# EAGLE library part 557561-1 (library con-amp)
AMP connector
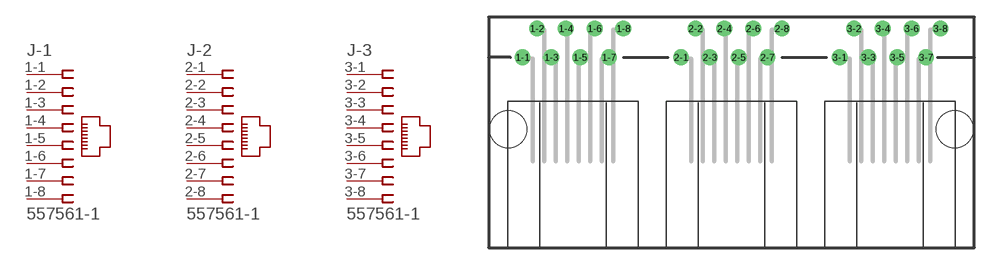
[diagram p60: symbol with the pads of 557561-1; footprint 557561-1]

Designator prefix J; gates -1=JACK8 -2=JACK8 -3=JACK8

## 557561-1 (MPN: 5557561-1; OC_FARNELL: 1769882; OC_NEWARK: 19R2785)  [557561-1]
1-1  -1:1  pas
1-2  -1:2  pas
1-3  -1:3  pas
1-4  -1:4  pas
1-5  -1:5  pas
1-6  -1:6  pas
1-7  -1:7  pas
1-8  -1:8  pas
2-1  -2:1  pas
2-2  -2:2  pas
2-3  -2:3  pas
2-4  -2:4  pas
2-5  -2:5  pas
2-6  -2:6  pas
2-7  -2:7  pas
2-8  -2:8  pas
3-1  -3:1  pas
3-2  -3:2  pas
3-3  -3:3  pas
3-4  -3:4  pas
3-5  -3:5  pas
3-6  -3:6  pas
3-7  -3:7  pas
3-8  -3:8  pas

## Footprint 557561-1 (pad centres in mm)
Modular Jack
drill 0.889 round: 1-1 -18.415,6.35; 1-2 -17.145,8.89; 1-3 -15.875,6.35; 1-4 -14.605,8.89; 1-5 -13.335,6.35; 1-6 -12.065,8.89; 1-7 -10.795,6.35; 1-8 -9.525,8.89; 2-1 -4.445,6.35; 2-2 -3.175,8.89; 2-3 -1.905,6.35; 2-4 -0.635,8.89; 2-5 0.635,6.35; 2-6 1.905,8.89; 2-7 3.175,6.35; 2-8 4.445,8.89; 3-1 9.525,6.35; 3-2 10.795,8.89; 3-3 12.065,6.35; 3-4 13.335,8.89; 3-5 14.605,6.35; 3-6 15.875,8.89; 3-7 17.145,6.35; 3-8 18.415,8.89
hole 3.251 at -19.685,0
hole 3.251 at 19.685,0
